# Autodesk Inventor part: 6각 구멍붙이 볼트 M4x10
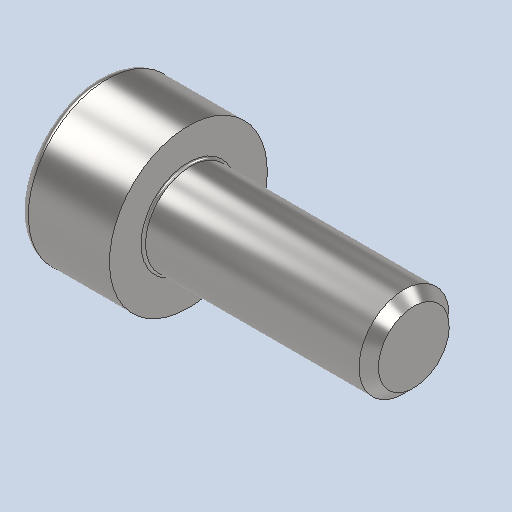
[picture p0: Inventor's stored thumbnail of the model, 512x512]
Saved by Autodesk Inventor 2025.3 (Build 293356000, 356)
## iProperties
Created: 2026-01
Part Number: 6각 구멍붙이 볼트 M4x10
Material: 강철, 연강
Description: 6각머리 태핑 나사
Document SubType Name: Modeling
Designer: PC-13
Density: 7.85 g/cm^3
Appearance: 기본값
Author: jhkim
Sending System: Autodesk Inventor 2026
Preprocessor: ST-DEVELOPER v20.1
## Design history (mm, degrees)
feature "Solid1"
node "솔리드1"
